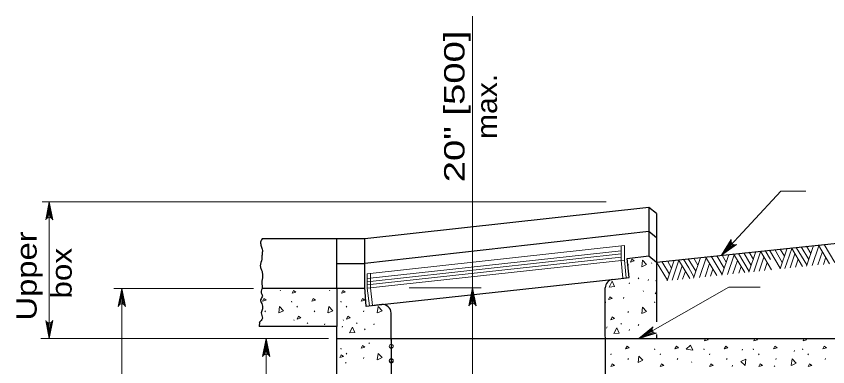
# Model space of a CAD drawing. Extents: x 1073.4 to 1107.4, y 719.4 to 741.4.
# Drawn here: x 1084.75 to 1091.11, y 728.23 to 730.97 of the extents above; entities that cross this region are included whole.
import ezdxf
from ezdxf.enums import TextEntityAlignment as Align

# ---------------------------------------------------------------- set-up
doc = ezdxf.new("R2010")
doc.units = 0
doc.header["$LTSCALE"] = 0.062
doc.header["$PDMODE"] = 32
doc.header["$PDSIZE"] = 0.031
doc.layers.add('1', color=7, linetype='Continuous', lineweight=13)

msp = doc.modelspace()

# ---------------------------------------------------------------- linework, layer by layer
at = {"layer": '1'}
for p, q in [((1088.32908, 727.71708), (1088.32908, 730.9745)), ((1089.37533, 729.5195), (1084.95642, 729.5195)), ((1084.99167, 729.38975), (1085.0115, 729.5195)), ((1085, 729.39475), (1085.0115, 729.5195)), ((1085.0115, 729.5195), (1085.0115, 728.44875)), ((1085.0115, 729.397), (1085.0115, 729.5195)), ((1085.02058, 729.39567), (1085.0115, 729.5195)), ((1085.02942, 729.39133), (1085.0115, 729.5195)), ((1089.519, 729.17758), (1087.50342, 728.95733)), ((1089.494, 729.06167), (1089.494, 729.17592)), ((1089.519, 729.0645), (1089.519, 729.17758)), ((1090.35558, 729.20817), (1090.28158, 729.102)), ((1090.35908, 729.199), (1090.28158, 729.102)), ((1090.36483, 729.19183), (1090.28158, 729.102)), ((1090.37483, 729.18575), (1090.28158, 729.102)), ((1090.38425, 729.18367), (1090.28158, 729.102)), ((1090.94558, 729.01608), (1091.00067, 729.1775)), ((1090.99158, 729.02108), (1091.04442, 729.17475)), ((1091.12817, 729.03533), (1091.04033, 729.18167)), ((1091.16992, 729.04408), (1091.08475, 729.18642)), ((1089.494, 729.13708), (1087.50342, 728.9195)), ((1089.494, 729.11192), (1087.50342, 728.89442)), ((1090.46325, 728.96542), (1090.37492, 729.11175)), ((1090.49758, 728.97383), (1090.41258, 729.11567)), ((1090.5135, 729.0205), (1090.45425, 729.12008)), ((1090.49567, 728.96883), (1090.55067, 729.13067)), ((1090.53008, 729.06908), (1090.49725, 729.12458)), ((1090.53392, 728.97283), (1090.587, 729.12917)), ((1090.6725, 728.98742), (1090.58508, 729.13375)), ((1090.66383, 729.06967), (1090.62333, 729.13783)), ((1090.74117, 728.99942), (1090.65625, 729.14133)), ((1090.75708, 729.04608), (1090.69783, 729.14558)), ((1090.73925, 728.99442), (1090.79425, 729.15625)), ((1090.77375, 729.09467), (1090.74083, 729.15017)), ((1090.7775, 728.99842), (1090.83058, 729.15475)), ((1090.8195, 729.00283), (1090.85633, 729.11242)), ((1090.91608, 729.01308), (1090.82875, 729.15942)), ((1090.9075, 729.09517), (1090.867, 729.16342)), ((1090.96375, 729.06925), (1090.90467, 729.16742)), ((1090.97958, 729.11583), (1090.94675, 729.17183)), ((1091.03558, 729.02558), (1091.07133, 729.13033)), ((1089.494, 729.08675), (1087.50342, 728.86917)), ((1089.51908, 729.06442), (1087.50342, 728.84408)), ((1089.50767, 728.92133), (1089.49417, 729.06167)), ((1089.53242, 728.92417), (1089.51908, 729.06417)), ((1089.85683, 728.9065), (1089.77192, 729.04842)), ((1089.87275, 728.95308), (1089.8135, 729.05267)), ((1089.85492, 728.9015), (1089.91, 729.06342)), ((1089.88942, 729.00175), (1089.8565, 729.05725)), ((1089.89317, 728.9055), (1089.94625, 729.06192)), ((1090.03183, 728.92008), (1089.94442, 729.0665)), ((1090.02317, 729.00225), (1089.98267, 729.0705)), ((1090.0795, 728.97625), (1090.02033, 729.0745)), ((1090.06133, 728.92325), (1090.11642, 729.0845)), ((1090.09525, 729.02292), (1090.0625, 729.07892)), ((1090.10725, 728.92808), (1090.16008, 729.08192)), ((1090.24383, 728.94242), (1090.156, 729.08875)), ((1090.28558, 728.95117), (1090.20058, 729.09342)), ((1090.3025, 729.00117), (1090.24492, 729.09808)), ((1090.284, 728.94667), (1090.339, 729.10783)), ((1090.31775, 729.04825), (1090.286, 729.10242)), ((1090.32658, 728.95108), (1090.379, 729.10442)), ((1090.3705, 728.95575), (1090.40583, 729.06033)), ((1090.576, 728.97725), (1090.61275, 729.08692)), ((1090.86017, 729.00708), (1090.8815, 729.07075)), ((1090.94892, 729.02608), (1090.9075, 729.09517)), ((1091.07892, 729.03025), (1091.09775, 729.08575)), ((1089.547, 729.02075), (1089.55042, 729.02842)), ((1089.73067, 729.04275), (1089.73425, 729.03742)), ((1089.93525, 728.91), (1089.972, 729.0195)), ((1090.06467, 728.93325), (1090.02317, 729.00225)), ((1090.15125, 728.93267), (1090.187, 729.03742)), ((1090.19467, 728.93733), (1090.2135, 728.99283)), ((1090.41542, 728.96042), (1090.43333, 729.0145)), ((1090.61658, 728.9815), (1090.63792, 729.04517)), ((1087.50342, 728.84408), (1087.50342, 728.95733)), ((1087.52842, 728.84592), (1087.52842, 728.95908)), ((1089.62767, 728.9175), (1089.63125, 728.9255)), ((1089.97583, 728.91425), (1089.99717, 728.97775)), ((1089.55575, 728.87858), (1089.55925, 728.88658)), ((1089.70592, 728.90483), (1089.70942, 728.91283)), ((1089.76617, 728.899), (1089.76967, 728.907)), ((1086.61225, 728.84233), (1085.51625, 728.84233)), ((1085.55942, 728.71258), (1085.57925, 728.84233)), ((1085.56767, 728.7175), (1085.57925, 728.84233)), ((1085.57925, 728.38208), (1085.57925, 728.84233)), ((1085.57925, 728.71975), (1085.57925, 728.84233)), ((1085.58825, 728.71842), (1085.57925, 728.84233)), ((1085.59717, 728.71408), (1085.57925, 728.84233)), ((1086.82125, 728.82742), (1086.82483, 728.82208)), ((1087.20783, 728.82742), (1087.21133, 728.82208)), ((1087.52058, 728.7045), (1087.50342, 728.84408)), ((1087.54533, 728.70692), (1087.52842, 728.84592)), ((1088.39567, 728.84592), (1087.83358, 728.84592)), ((1088.30925, 728.71617), (1088.32908, 728.84592)), ((1088.31758, 728.72108), (1088.32908, 728.84592)), ((1088.32908, 728.72342), (1088.32908, 728.84592)), ((1088.33817, 728.72208), (1088.32908, 728.84592)), ((1088.347, 728.71775), (1088.32908, 728.84592)), ((1089.63267, 728.44875), (1090.33792, 728.85058)), ((1089.66667, 728.82175), (1089.67025, 728.81642)), ((1089.772, 728.8025), (1089.75992, 728.79875)), ((1090.58425, 728.85058), (1090.33792, 728.85058)), ((1086.91092, 728.74217), (1086.91183, 728.73425)), ((1087.29758, 728.74217), (1087.29842, 728.73425)), ((1089.36992, 728.73658), (1089.37075, 728.72875)), ((1089.51175, 728.76408), (1089.51533, 728.77208)), ((1089.7565, 728.73658), (1089.75733, 728.72875)), ((1086.70133, 728.65875), (1086.70492, 728.66675)), ((1086.95308, 728.69508), (1086.95658, 728.70308)), ((1087.088, 728.65875), (1087.09158, 728.66675)), ((1087.33967, 728.69508), (1087.34325, 728.70308)), ((1087.47458, 728.65875), (1087.47817, 728.66675)), ((1089.54692, 728.65308), (1089.55042, 728.66108)), ((1084.99358, 728.57692), (1085.0115, 728.44875)), ((1085.0025, 728.57258), (1085.0115, 728.44875)), ((1085.03133, 728.57842), (1085.0115, 728.44875)), ((1085.023, 728.5735), (1085.0115, 728.44875)), ((1085.0115, 728.57125), (1085.0115, 728.44875)), ((1086.92292, 728.54242), (1086.92425, 728.54525)), ((1086.92733, 728.59575), (1086.93092, 728.59042)), ((1087.03367, 728.57317), (1087.03725, 728.56783)), ((1087.16875, 728.55575), (1087.17225, 728.56375)), ((1087.30725, 728.53725), (1087.31075, 728.54525)), ((1087.31392, 728.59575), (1087.3175, 728.59042)), ((1087.42025, 728.57317), (1087.42383, 728.56783)), ((1087.55525, 728.55575), (1087.55892, 728.56375)), ((1089.3795, 728.53167), (1089.38308, 728.53967)), ((1089.49258, 728.56758), (1089.49617, 728.56225)), ((1089.62767, 728.55017), (1089.63125, 728.55817)), ((1087.48342, 728.51675), (1087.487, 728.52475)), ((1089.55575, 728.51125), (1089.55925, 728.51925)), ((1089.73675, 728.52575), (1089.63267, 728.44875)), ((1089.73717, 728.51583), (1089.63267, 728.44875)), ((1089.74033, 728.50725), (1089.63267, 728.44875)), ((1089.74783, 728.49825), (1089.63267, 728.44875)), ((1089.75608, 728.49325), (1089.63267, 728.44875)), ((1086.69217, 728.319), (1086.71208, 728.44875)), ((1086.7005, 728.32392), (1086.71208, 728.44875)), ((1086.71208, 727.21808), (1086.71208, 728.44875)), ((1086.71208, 728.32617), (1086.71208, 728.44875)), ((1086.72117, 728.32483), (1086.71208, 728.44875)), ((1086.73, 728.3205), (1086.71208, 728.44875)), ((1087.51717, 728.41533), (1087.52067, 728.41)), ((1087.68758, 728.437), (1087.69092, 728.44392)), ((1087.69092, 728.43808), (1087.68758, 728.437)), ((1089.66667, 728.45442), (1089.67025, 728.44908)), ((1090.1465, 728.43142), (1090.15483, 728.44875)), ((1090.53308, 728.43142), (1090.54133, 728.44875)), ((1090.78908, 728.44875), (1090.78692, 728.44833)), ((1090.7885, 728.44858), (1090.78733, 728.44875)), ((1090.91967, 728.43142), (1090.928, 728.44875)), ((1085.57925, 728.38208), (1085.57925, 724.04508)), ((1087.29758, 728.37492), (1087.29842, 728.36692)), ((1087.69133, 728.38842), (1087.69133, 728.38875)), ((1089.36992, 728.36883), (1089.37075, 728.36142)), ((1089.7565, 728.36942), (1089.75733, 728.36142)), ((1090.143, 728.36942), (1090.14392, 728.36142)), ((1090.44283, 728.3575), (1090.44633, 728.3655)), ((1090.52958, 728.36942), (1090.5305, 728.36142)), ((1090.84942, 728.34842), (1090.853, 728.35642)), ((1090.91625, 728.36942), (1090.91717, 728.36142)), ((1087.33967, 728.32775), (1087.34325, 728.33575)), ((1087.47458, 728.29142), (1087.47817, 728.29942)), ((1089.41192, 728.32225), (1089.4155, 728.33025)), ((1089.54692, 728.28575), (1089.55042, 728.29375)), ((1089.79858, 728.32225), (1089.80208, 728.33025)), ((1089.9335, 728.28575), (1089.93708, 728.29375)), ((1090.18517, 728.32225), (1090.18867, 728.33025)), ((1090.32008, 728.28575), (1090.32358, 728.29375)), ((1090.57175, 728.32225), (1090.57525, 728.33025)), ((1090.70658, 728.28575), (1090.71025, 728.29375)), ((1090.95825, 728.32225), (1090.96192, 728.33025)), ((1091.09325, 728.28575), (1091.09675, 728.29375)), ((1087.33425, 728.26233), (1087.33775, 728.257)), ((1087.69133, 728.27508), (1087.69133, 728.275)), ((1087.69133, 728.27458), (1087.69133, 728.27442)), ((1087.69133, 728.27425), (1087.69133, 728.27408)), ((1087.69133, 728.27317), (1087.69133, 728.27308)), ((1087.69133, 728.27283), (1087.69133, 728.27275)), ((1090.04533, 728.26583), (1090.04892, 728.2605)), ((1090.36292, 728.23117), (1090.3665, 728.23917)), ((1090.69367, 728.23475), (1090.69725, 728.22942))]:
    msp.add_line(p, q, dxfattribs=at)
at = {"layer": '1', "lineweight": 25}
for p, q in [((1089.70958, 729.47683), (1087.48558, 729.22958)), ((1089.772, 729.42867), (1089.772, 729.04842)), ((1087.48558, 729.22958), (1086.67892, 729.22958)), ((1087.26608, 728.84233), (1087.26608, 729.22958)), ((1087.48558, 728.84233), (1087.48558, 729.22958)), ((1089.772, 729.04842), (1091.48392, 729.22825)), ((1089.772, 729.04842), (1089.772, 728.58108)), ((1087.26608, 729.03642), (1087.48558, 729.03642)), ((1089.42892, 728.91267), (1089.55725, 728.92675)), ((1087.54533, 728.70692), (1089.44358, 728.91442)), ((1087.48558, 728.84233), (1086.67892, 728.84233)), ((1087.49575, 728.70142), (1087.48492, 728.85133)), ((1089.37025, 727.99275), (1089.36958, 728.84642)), ((1087.61708, 728.71475), (1087.49575, 728.70142)), ((1087.69092, 728.44875), (1087.69092, 728.64842)), ((1086.65858, 728.57675), (1086.65525, 728.54242)), ((1087.26608, 728.54242), (1086.65525, 728.54242)), ((1089.772, 728.48117), (1089.772, 728.44875)), ((1087.26608, 728.44875), (1088.59667, 728.44875)), ((1087.69092, 728.44875), (1087.69092, 724.04508)), ((1088.59667, 728.44875), (1092.41392, 728.44875))]:
    msp.add_line(p, q, dxfattribs=at)
at = {"layer": '1'}
for points in [[(1090.28158, 729.102), (1090.74658, 729.60358), (1090.9415, 729.60358)], [(1084.98325, 729.37792), (1085.0115, 729.5195), (1085.03983, 729.37792)], [(1090.39858, 729.18658), (1090.28158, 729.102), (1090.357, 729.22508)], [(1089.65492, 729.01133), (1089.66192, 729.06208), (1089.69367, 729.02917), (1089.65575, 729.01158)], [(1089.40025, 728.85208), (1089.42425, 728.89742), (1089.44292, 728.85567), (1089.40117, 728.85208)], [(1085.55092, 728.70075), (1085.57925, 728.84233), (1085.60758, 728.70075)], [(1088.30075, 728.70433), (1088.32908, 728.84592), (1088.35742, 728.70433)], [(1089.75992, 728.79875), (1089.77058, 728.82092), (1089.772, 728.81983)], [(1086.80942, 728.6495), (1086.81642, 728.70033), (1086.84817, 728.66742), (1086.81025, 728.64983)], [(1087.19592, 728.6495), (1087.203, 728.70033), (1087.23483, 728.66742), (1087.19683, 728.64983)], [(1087.58258, 728.6495), (1087.58958, 728.70033), (1087.62133, 728.66742), (1087.58333, 728.64983)], [(1089.65492, 728.644), (1089.66192, 728.69475), (1089.69367, 728.66183), (1089.65575, 728.64425)], [(1085.03983, 728.59033), (1085.0115, 728.44875), (1084.98325, 728.59033)], [(1087.36358, 728.49292), (1087.38758, 728.53808), (1087.40625, 728.49642), (1087.36458, 728.49292)], [(1089.77058, 728.49142), (1089.63267, 728.44875), (1089.74358, 728.54125)], [(1089.43592, 728.48733), (1089.45992, 728.5325), (1089.47858, 728.49092), (1089.43683, 728.48733)], [(1087.1995, 728.44875), (1086.38017, 728.44875), (1084.94492, 728.44875)], [(1086.68375, 728.30708), (1086.71208, 728.44875), (1086.74042, 728.30708)], [(1090.16358, 728.44875), (1090.17492, 728.44025), (1090.1465, 728.43142)], [(1090.55017, 728.44875), (1090.5615, 728.44025), (1090.53308, 728.43142)], [(1090.93675, 728.44875), (1090.948, 728.44025), (1090.91967, 728.43142)], [(1090.05492, 728.35775), (1090.00417, 728.36475), (1090.037, 728.39642), (1090.05458, 728.3585)], [(1087.58258, 728.28217), (1087.58958, 728.333), (1087.62133, 728.30008), (1087.58333, 728.2825)], [(1089.626, 728.26067), (1089.63308, 728.31133), (1089.66483, 728.27842), (1089.62692, 728.26092)], [(1090.47217, 728.28775), (1090.46508, 728.23708), (1090.43325, 728.26992), (1090.47125, 728.28742)], [(1090.82742, 728.23817), (1090.83442, 728.28883), (1090.86625, 728.25608), (1090.82825, 728.23842)], [(1087.69133, 728.27858), (1087.69133, 728.27842), (1087.69133, 728.27833), (1087.69133, 728.27817), (1087.69133, 728.27808), (1087.69133, 728.27792), (1087.69133, 728.27775), (1087.69133, 728.27767), (1087.69133, 728.2775), (1087.69133, 728.27742), (1087.69133, 728.27725), (1087.69133, 728.27708), (1087.69133, 728.277), (1087.69133, 728.27692), (1087.69133, 728.27683), (1087.69133, 728.27675)], [(1087.69133, 728.27675), (1087.69133, 728.27667), (1087.69133, 728.27658), (1087.69133, 728.2765), (1087.69133, 728.27642)], [(1087.69133, 728.27642), (1087.69133, 728.27633), (1087.69133, 728.27625), (1087.69133, 728.27617), (1087.69133, 728.27608)], [(1087.69133, 728.27608), (1087.69133, 728.276), (1087.69133, 728.27592), (1087.69133, 728.27583), (1087.69133, 728.27575)], [(1087.69133, 728.27575), (1087.69133, 728.27567), (1087.69133, 728.27558), (1087.69133, 728.2755), (1087.69133, 728.27542)], [(1087.69133, 728.27542), (1087.69133, 728.27533), (1087.69133, 728.27525), (1087.69133, 728.27517), (1087.69133, 728.27508)], [(1087.69133, 728.275), (1087.69133, 728.27483), (1087.69133, 728.27475)], [(1087.69133, 728.27475), (1087.69133, 728.27467), (1087.69133, 728.27458)], [(1087.69133, 728.27442), (1087.69133, 728.27433), (1087.69133, 728.27425)], [(1087.69133, 728.27408), (1087.69133, 728.274), (1087.69133, 728.27392)], [(1087.69133, 728.27392), (1087.69133, 728.27383), (1087.69133, 728.27375), (1087.69133, 728.27367), (1087.69133, 728.27358), (1087.69133, 728.2735)], [(1087.69133, 728.2735), (1087.69133, 728.27342), (1087.69133, 728.27333), (1087.69133, 728.27325), (1087.69133, 728.27317)], [(1087.69133, 728.27308), (1087.69133, 728.27292), (1087.69133, 728.27283)], [(1087.69133, 728.27275), (1087.69133, 728.27258), (1087.69133, 728.2725), (1087.69133, 728.27242)]]:
    msp.add_lwpolyline(points, dxfattribs=at)
at = {"layer": '1', "lineweight": 25}
for points in [[(1089.772, 729.42867), (1089.70958, 729.47683), (1089.70958, 729.09658)], [(1089.772, 729.23842), (1089.70958, 729.28675), (1087.48558, 729.03592)], [(1089.55725, 728.92675), (1089.54092, 729.07592), (1089.70958, 729.09658), (1089.772, 729.04842)], [(1087.26608, 728.84233), (1087.26608, 728.61742), (1087.26608, 728.54242)], [(1092.41392, 723.54533), (1087.26608, 723.54533), (1087.26608, 728.54242)]]:
    msp.add_lwpolyline(points, dxfattribs=at)
at = {"layer": '1'}
for points in [[(1089.56683, 729.04783), (1089.5775, 729.07008), (1089.59525, 729.05675)], [(1086.91442, 728.80433), (1086.92508, 728.8265), (1086.94283, 728.81317)], [(1087.301, 728.80433), (1087.31158, 728.8265), (1087.32942, 728.81317)], [(1086.68383, 728.74075), (1086.69442, 728.763), (1086.71225, 728.74975)], [(1087.07042, 728.74075), (1087.08108, 728.763), (1087.09883, 728.74975)], [(1087.457, 728.74075), (1087.46758, 728.763), (1087.48542, 728.74975)], [(1089.39417, 728.75442), (1089.40483, 728.77658), (1089.42258, 728.76325)], [(1086.95492, 728.602), (1086.96558, 728.62408), (1086.98325, 728.61083)], [(1087.34142, 728.602), (1087.35208, 728.62408), (1087.36992, 728.61083)], [(1089.41375, 728.59642), (1089.42433, 728.61858), (1089.44217, 728.60525)], [(1087.457, 728.3735), (1087.46758, 728.39567), (1087.48542, 728.38242)], [(1089.52925, 728.368), (1089.53992, 728.39008), (1089.55767, 728.37683)], [(1089.91592, 728.368), (1089.92658, 728.39008), (1089.94425, 728.37683)], [(1090.3025, 728.368), (1090.31317, 728.39008), (1090.33092, 728.37683)], [(1090.68908, 728.368), (1090.69967, 728.39008), (1090.7175, 728.37683)], [(1091.07558, 728.368), (1091.08625, 728.39008), (1091.104, 728.37683)], [(1087.28825, 728.29942), (1087.29892, 728.32167), (1087.31675, 728.30833)], [(1089.41375, 728.22908), (1089.42433, 728.25125), (1089.44217, 728.23792)], [(1089.80033, 728.22908), (1089.81092, 728.25125), (1089.82867, 728.23792)], [(1090.18692, 728.22908), (1090.19758, 728.25125), (1090.21533, 728.23792)], [(1090.5735, 728.22908), (1090.58417, 728.25125), (1090.60192, 728.23792)], [(1090.96008, 728.22908), (1090.97075, 728.25125), (1090.9885, 728.23792)]]:
    msp.add_lwpolyline(points, close=True, dxfattribs=at)
for centre, start, end in [((1085.01155, 729.36648), 22.08782, 157.91395), ((1090.38557, 729.21424), 159.25021, 295.07634), ((1085.57926, 728.68925), 22.08782, 157.91395), ((1088.32911, 728.69285), 22.08782, 157.91395), ((1085.01148, 728.60175), 202.08782, 337.91395), ((1089.76713, 728.52184), 140.59405, 276.42018), ((1086.71208, 728.29568), 22.08782, 157.91395)]:
    msp.add_arc(centre, 0.03056, start, end, dxfattribs=at)
at = {"layer": '1', "lineweight": 25}
for centre, major_axis, start_param, end_param in [((1089.43623, 728.84641), (-0.06664, 0), 4.8215662, 6.2838842), ((1087.62428, 728.64849), (0.06664, 0), 6.2831853, 7.9626685)]:
    msp.add_ellipse(centre, major_axis=major_axis, ratio=0.999895, start_param=start_param, end_param=end_param, dxfattribs=at)
for points in [[(1086.67892, 729.22958), (1086.66808, 729.20533), (1086.67275, 729.17267), (1086.68208, 729.13992), (1086.679, 729.10408), (1086.67742, 729.07142), (1086.66492, 729.01992), (1086.67275, 728.99183), (1086.68058, 728.96692), (1086.68058, 728.91092), (1086.67742, 728.88592), (1086.679, 728.86258), (1086.67892, 728.84233)], [(1086.67892, 728.84233), (1086.67342, 728.8205), (1086.67617, 728.79625), (1086.6815, 728.78283), (1086.66808, 728.75325), (1086.67617, 728.72375), (1086.6815, 728.68067), (1086.67342, 728.65108), (1086.6815, 728.60808), (1086.65525, 728.57392)]]:
    msp.add_spline(points, degree=3, dxfattribs=at)
at = {"layer": '1'}
for p in [(1087.69133, 728.38875), (1087.69133, 728.27675), (1087.69133, 728.27642), (1087.69133, 728.27608), (1087.69133, 728.27575), (1087.69133, 728.27542), (1087.69133, 728.27508), (1087.69133, 728.275), (1087.69133, 728.27475), (1087.69133, 728.27458), (1087.69133, 728.27442), (1087.69133, 728.27425), (1087.69133, 728.27408), (1087.69133, 728.27392), (1087.69133, 728.2735), (1087.69133, 728.27317), (1087.69133, 728.27308), (1087.69133, 728.27283), (1087.69133, 728.27275)]:
    msp.add_point(p, dxfattribs=at)

# ---------------------------------------------------------------- texts
for s, width, p in [('20" [500]', 1.4, (1088.26633, 730.26792)), ('max.', 1.1, (1088.52075, 730.26792)), ('Upper', 1.2, (1084.91233, 728.9395)), ('box', 1.15, (1085.18683, 728.96062))]:
    msp.add_text(s, height=0.16, rotation=90, dxfattribs=dict(at, width=width)).set_placement(p, align=Align.CENTER)

doc.saveas('drawing.dxf')
